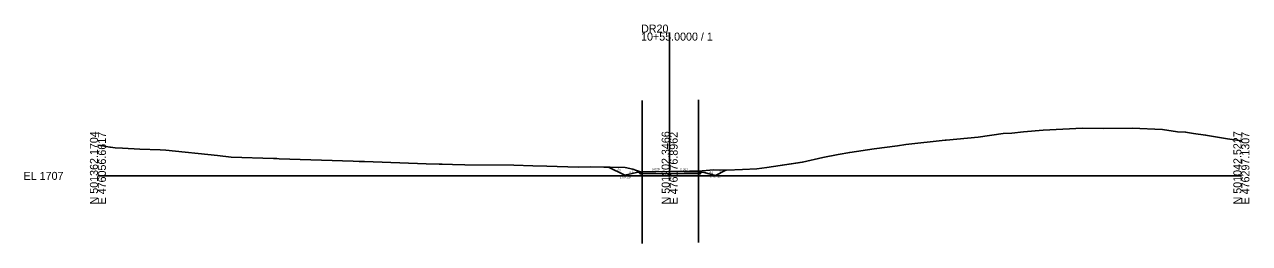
# Model space of a CAD drawing. Extents: x 78027 to 79855, y -93601 to -93005.
# Drawn here: x 78026.8 to 78455.3, y -93600.9 to -93524.2 of the extents above; entities that cross this region are included whole.
import ezdxf

# ---------------------------------------------------------------- set-up
doc = ezdxf.new("R2010")
doc.units = 0
for name, color, linetype in [('Exist Cross Section Cell', 7, 'Continuous'), ('Exist XS Center Line Elevation Label', 7, 'Continuous'), ('Exist XS Ground Line', 7, 'Continuous'), ('Prop XS Ditch Slope Text', 7, 'Continuous'), ('Prop XS Ditch Standard Text', 7, 'Continuous'), ('Prop XS Earthwork Shape', 7, 'Continuous'), ('Prop XS EOT Tick Mark', 7, 'Continuous'), ('Prop XS Finish Grade', 7, 'Continuous'), ('Prop XS Finish Grade Earthwork', 7, 'Continuous'), ('Prop XS Finish Grade Pavement', 7, 'Continuous'), ('Prop XS Pvmt Edge Slope', 7, 'Continuous'), ('Prop XS SE Text', 7, 'Continuous'), ('Prop XS Shoulder Borrow Shape', 7, 'Continuous'), ('Prop XS Side Slope Text', 7, 'Continuous'), ('Prop XS Subgrade Earthwork', 7, 'Continuous'), ('Scratch_Level_0', 7, 'Continuous'), ('Scratch_Level_4', 7, 'Continuous'), ('Scratch_Level_5', 7, 'Continuous'), ('Scratch_Level_6', 7, 'Continuous')]:
    doc.layers.add(name, color=color, linetype=linetype)

msp = doc.modelspace()

# ---------------------------------------------------------------- linework, layer by layer
at = {"layer": 'Exist Cross Section Cell'}
for p, q in [((78252.48, -93577.22), (78252.48, -93527.07)), ((78052.48, -93577.22), (78252.48, -93577.22)), ((78252.48, -93577.22), (78452.48, -93577.22))]:
    msp.add_line(p, q, dxfattribs=at)
at = {"layer": 'Exist XS Ground Line'}
for p, q in [((78376.27, -93561.79), (78383.1, -93561.24)), ((78383.1, -93561.24), (78396.9, -93560.55)), ((78396.9, -93560.55), (78404.42, -93560.58)), ((78404.42, -93560.58), (78414.28, -93560.5)), ((78414.28, -93560.5), (78424.94, -93561.02)), ((78424.94, -93561.02), (78430.15, -93561.75)), ((78335.05, -93566.25), (78348.83, -93564.73)), ((78348.83, -93564.73), (78349.16, -93564.7)), ((78349.16, -93564.7), (78360.37, -93563.66)), ((78360.37, -93563.66), (78369.1, -93562.44)), ((78369.1, -93562.44), (78372.19, -93562.24)), ((78372.19, -93562.24), (78376.27, -93561.79)), ((78430.15, -93561.75), (78432.97, -93561.87)), ((78432.97, -93561.87), (78435.77, -93562.4)), ((78435.77, -93562.4), (78439.95, -93562.93)), ((78439.95, -93562.93), (78447.6, -93564.25)), ((78447.6, -93564.25), (78452.48, -93565.01)), ((78052.48, -93566.51), (78053.5, -93566.59)), ((78053.5, -93566.59), (78054.08, -93566.65)), ((78054.08, -93566.65), (78056.61, -93567.15)), ((78056.61, -93567.15), (78056.93, -93567.19)), ((78056.93, -93567.19), (78058.54, -93567.38)), ((78058.54, -93567.38), (78061.04, -93567.5)), ((78061.04, -93567.5), (78067.08, -93567.88)), ((78067.08, -93567.88), (78074.23, -93568.09)), ((78074.23, -93568.09), (78076.18, -93568.19)), ((78076.18, -93568.19), (78094.33, -93570.14)), ((78306.07, -93570.81), (78311.48, -93569.76)), ((78311.48, -93569.76), (78315.51, -93568.98)), ((78315.51, -93568.98), (78324, -93567.81)), ((78324, -93567.81), (78332.15, -93566.72)), ((78332.15, -93566.72), (78335.05, -93566.25)), ((78094.33, -93570.14), (78099.14, -93570.63)), ((78099.14, -93570.63), (78113.88, -93571.15)), ((78113.88, -93571.15), (78114.68, -93571.19)), ((78114.68, -93571.19), (78115.12, -93571.19)), ((78115.12, -93571.19), (78115.87, -93571.21)), ((78115.87, -93571.21), (78141.82, -93572.08)), ((78141.82, -93572.08), (78143.84, -93572.14)), ((78143.84, -93572.14), (78145.77, -93572.18)), ((78145.77, -93572.18), (78167.26, -93572.98)), ((78167.26, -93572.98), (78171.85, -93573.11)), ((78171.85, -93573.11), (78172.92, -93573.12)), ((78172.92, -93573.12), (78176.48, -93573.28)), ((78176.48, -93573.28), (78180.8, -93573.32)), ((78180.8, -93573.32), (78198.01, -93573.52)), ((78198.01, -93573.52), (78204.61, -93573.74)), ((78204.61, -93573.74), (78209.53, -93573.8)), ((78209.53, -93573.8), (78220.48, -93574.16)), ((78220.48, -93574.16), (78224.92, -93574.06)), ((78224.92, -93574.06), (78229.49, -93574.2)), ((78229.49, -93574.2), (78231.67, -93574.12)), ((78231.67, -93574.12), (78236.86, -93574.29)), ((78236.86, -93574.29), (78239.63, -93574.89)), ((78282.92, -93574.78), (78286.45, -93574.34)), ((78286.45, -93574.34), (78298.88, -93572.44)), ((78298.88, -93572.44), (78298.97, -93572.41)), ((78298.97, -93572.41), (78306.07, -93570.81)), ((78239.63, -93574.89), (78240.83, -93575.37)), ((78240.83, -93575.37), (78241.94, -93575.67)), ((78241.94, -93575.67), (78242.84, -93575.89)), ((78242.84, -93575.89), (78252.41, -93575.67)), ((78252.41, -93575.67), (78252.48, -93575.67)), ((78252.48, -93575.67), (78259.43, -93575.62)), ((78259.43, -93575.62), (78262.52, -93575.55)), ((78262.52, -93575.55), (78267.84, -93575.08)), ((78267.84, -93575.08), (78272.44, -93575.21)), ((78272.44, -93575.21), (78277.97, -93574.99)), ((78277.97, -93574.99), (78282.92, -93574.78))]:
    msp.add_line(p, q, dxfattribs=at)
at = {"layer": 'Prop XS Earthwork Shape'}
msp.add_lwpolyline([(78231.09, -93574.15), (78231.67, -93574.12), (78236.86, -93574.29), (78239.63, -93574.89), (78240.83, -93575.37), (78241.94, -93575.67), (78242.84, -93575.89), (78252.41, -93575.67), (78252.48, -93575.67), (78259.43, -93575.62), (78262.52, -93575.55), (78267.84, -93575.08), (78272.19, -93575.2), (78268.53, -93577.03), (78264.53, -93576.03), (78263.79, -93575.97), (78263.21, -93576.55), (78262.52, -93576.53), (78252.48, -93576.33), (78242.84, -93576.53), (78242.16, -93576.54), (78241.58, -93575.96), (78240.84, -93576.02), (78236.84, -93577.02)], close=True, dxfattribs=at)
msp.add_lwpolyline([(78231.09, -93574.15), (78231.67, -93574.12), (78236.86, -93574.29), (78239.63, -93574.89), (78240.83, -93575.37), (78241.94, -93575.67), (78242.84, -93575.89), (78252.41, -93575.67), (78252.48, -93575.67), (78259.43, -93575.62), (78262.52, -93575.55), (78267.84, -93575.08), (78272.19, -93575.2), (78268.53, -93577.03), (78264.53, -93576.03), (78263.79, -93575.97), (78263.21, -93576.55), (78262.52, -93576.53), (78252.48, -93576.33), (78242.84, -93576.53), (78242.16, -93576.54), (78241.58, -93575.96), (78240.84, -93576.02), (78236.84, -93577.02)], close=True, dxfattribs=at)
at = {"layer": 'Prop XS EOT Tick Mark'}
for p, q in [((78242.84, -93575.86), (78242.84, -93574.86)), ((78262.52, -93575.87), (78262.52, -93574.87))]:
    msp.add_line(p, q, dxfattribs=at)
at = {"layer": 'Prop XS Finish Grade'}
for p, q in [((78242.84, -93575.86), (78241.58, -93575.96)), ((78262.52, -93575.87), (78263.79, -93575.97))]:
    msp.add_line(p, q, dxfattribs=at)
at = {"layer": 'Prop XS Finish Grade Earthwork'}
for p, q in [((78236.84, -93577.02), (78231.09, -93574.15)), ((78240.84, -93576.02), (78236.84, -93577.02)), ((78241.58, -93575.96), (78240.84, -93576.02)), ((78263.79, -93575.97), (78264.53, -93576.03)), ((78264.53, -93576.03), (78268.53, -93577.03)), ((78268.53, -93577.03), (78272.19, -93575.2))]:
    msp.add_line(p, q, dxfattribs=at)
at = {"layer": 'Prop XS Finish Grade Pavement'}
for p, q in [((78242.84, -93575.86), (78252.48, -93575.67)), ((78252.48, -93575.67), (78262.52, -93575.87))]:
    msp.add_line(p, q, dxfattribs=at)
at = {"layer": 'Prop XS Pvmt Edge Slope'}
for p, q in [((78242.84, -93575.86), (78242.16, -93576.54)), ((78262.52, -93575.87), (78263.21, -93576.55))]:
    msp.add_line(p, q, dxfattribs=at)
at = {"layer": 'Prop XS Shoulder Borrow Shape'}
for points in [[(78242.74, -93575.87), (78242.81, -93575.88), (78242.16, -93576.54), (78241.58, -93575.96)], [(78242.74, -93575.87), (78242.81, -93575.88), (78242.84, -93575.86)], [(78263.21, -93576.55), (78263.79, -93575.97), (78262.52, -93575.87)]]:
    msp.add_lwpolyline(points, close=True, dxfattribs=at)
at = {"layer": 'Prop XS Subgrade Earthwork'}
for p, q in [((78242.16, -93576.54), (78241.58, -93575.96)), ((78242.84, -93576.53), (78242.16, -93576.54)), ((78252.48, -93576.33), (78242.84, -93576.53)), ((78262.52, -93576.53), (78252.48, -93576.33)), ((78262.52, -93576.53), (78263.21, -93576.55)), ((78263.21, -93576.55), (78263.79, -93575.97))]:
    msp.add_line(p, q, dxfattribs=at)
at = {"layer": 'Scratch_Level_0'}
msp.add_lwpolyline([(78052.48, -93566.51), (78053.5, -93566.59), (78054.08, -93566.65), (78056.61, -93567.15), (78056.93, -93567.19), (78058.54, -93567.38), (78061.04, -93567.5), (78067.08, -93567.88), (78074.23, -93568.09), (78076.18, -93568.19), (78094.33, -93570.14), (78099.14, -93570.63), (78113.88, -93571.15), (78114.68, -93571.19), (78115.12, -93571.19), (78115.87, -93571.21), (78141.82, -93572.08), (78143.84, -93572.14), (78145.77, -93572.18), (78167.26, -93572.98), (78171.85, -93573.11), (78172.92, -93573.12), (78176.48, -93573.28), (78180.8, -93573.32), (78198.01, -93573.52), (78204.61, -93573.74), (78209.53, -93573.8), (78220.48, -93574.16), (78224.92, -93574.06), (78229.49, -93574.2), (78231.67, -93574.12), (78236.86, -93574.29), (78239.63, -93574.89), (78240.83, -93575.37), (78241.94, -93575.67), (78242.84, -93575.89), (78252.48, -93575.67), (78259.43, -93575.62), (78262.52, -93575.55), (78267.84, -93575.08), (78272.44, -93575.21), (78277.97, -93574.99), (78282.92, -93574.78), (78286.45, -93574.34), (78298.97, -93572.41), (78306.07, -93570.81), (78311.48, -93569.76), (78315.51, -93568.98), (78324, -93567.81), (78332.15, -93566.72), (78335.05, -93566.25), (78348.83, -93564.73), (78349.16, -93564.7), (78360.37, -93563.66), (78369.1, -93562.44), (78372.19, -93562.24), (78376.27, -93561.79), (78383.1, -93561.24), (78396.9, -93560.55), (78404.42, -93560.58), (78414.28, -93560.5), (78424.94, -93561.02), (78430.15, -93561.75), (78432.97, -93561.87), (78435.77, -93562.4), (78439.95, -93562.93), (78447.6, -93564.25), (78452.48, -93565.01)], dxfattribs=at)
at = {"layer": 'Scratch_Level_4'}
for p, q in [((78242.84, -93550.89), (78242.84, -93600.89)), ((78242.84, -93550.89), (78242.84, -93600.89)), ((78262.52, -93550.55), (78262.52, -93600.55)), ((78262.52, -93550.55), (78262.52, -93600.55))]:
    msp.add_line(p, q, dxfattribs=at)
at = {"layer": 'Scratch_Level_5'}
msp.add_lwpolyline([(78052.48, -93566.51), (78053.5, -93566.59), (78054.08, -93566.65), (78056.61, -93567.15), (78056.93, -93567.19), (78058.54, -93567.38), (78061.04, -93567.5), (78067.08, -93567.88), (78074.23, -93568.09), (78076.18, -93568.19), (78094.33, -93570.14), (78099.14, -93570.63), (78113.88, -93571.15), (78114.68, -93571.19), (78115.12, -93571.19), (78115.87, -93571.21), (78141.82, -93572.08), (78143.84, -93572.14), (78145.77, -93572.18), (78167.26, -93572.98), (78171.85, -93573.11), (78172.92, -93573.12), (78176.48, -93573.28), (78180.8, -93573.32), (78198.01, -93573.52), (78204.61, -93573.74), (78209.53, -93573.8), (78220.48, -93574.16), (78224.92, -93574.06), (78229.49, -93574.2), (78231.67, -93574.12), (78236.86, -93574.29), (78239.63, -93574.89), (78240.83, -93575.37), (78241.94, -93575.67), (78242.84, -93575.89), (78252.48, -93575.67), (78259.43, -93575.62), (78262.52, -93575.55), (78267.84, -93575.08), (78272.44, -93575.21), (78277.97, -93574.99), (78282.92, -93574.78), (78286.45, -93574.34), (78298.97, -93572.41), (78306.07, -93570.81), (78311.48, -93569.76), (78315.51, -93568.98), (78324, -93567.81), (78332.15, -93566.72), (78335.05, -93566.25), (78348.83, -93564.73), (78349.16, -93564.7), (78360.37, -93563.66), (78369.1, -93562.44), (78372.19, -93562.24), (78376.27, -93561.79), (78383.1, -93561.24), (78396.9, -93560.55), (78404.42, -93560.58), (78414.28, -93560.5), (78424.94, -93561.02), (78430.15, -93561.75), (78432.97, -93561.87), (78435.77, -93562.4), (78439.95, -93562.93), (78447.6, -93564.25), (78452.48, -93565.01)], dxfattribs=at)
at = {"layer": 'Scratch_Level_6'}
msp.add_lwpolyline([(78052.48, -93566.51), (78053.5, -93566.59), (78054.08, -93566.65), (78056.61, -93567.15), (78056.93, -93567.19), (78058.54, -93567.38), (78061.04, -93567.5), (78067.08, -93567.88), (78074.23, -93568.09), (78076.18, -93568.19), (78094.33, -93570.14), (78099.14, -93570.63), (78113.88, -93571.15), (78114.68, -93571.19), (78115.12, -93571.19), (78115.87, -93571.21), (78141.82, -93572.08), (78143.84, -93572.14), (78145.77, -93572.18), (78167.26, -93572.98), (78171.85, -93573.11), (78172.92, -93573.12), (78176.48, -93573.28), (78180.8, -93573.32), (78198.01, -93573.52), (78204.61, -93573.74), (78209.53, -93573.8), (78220.48, -93574.16), (78224.92, -93574.06), (78229.49, -93574.2), (78231.67, -93574.12), (78236.86, -93574.29), (78239.63, -93574.89), (78240.83, -93575.37), (78241.94, -93575.67), (78242.84, -93575.89), (78252.48, -93575.67), (78259.43, -93575.62), (78262.52, -93575.55), (78267.84, -93575.08), (78272.44, -93575.21), (78277.97, -93574.99), (78282.92, -93574.78), (78286.45, -93574.34), (78298.97, -93572.41), (78306.07, -93570.81), (78311.48, -93569.76), (78315.51, -93568.98), (78324, -93567.81), (78332.15, -93566.72), (78335.05, -93566.25), (78348.83, -93564.73), (78349.16, -93564.7), (78360.37, -93563.66), (78369.1, -93562.44), (78372.19, -93562.24), (78376.27, -93561.79), (78383.1, -93561.24), (78396.9, -93560.55), (78404.42, -93560.58), (78414.28, -93560.5), (78424.94, -93561.02), (78430.15, -93561.75), (78432.97, -93561.87), (78435.77, -93562.4), (78439.95, -93562.93), (78447.6, -93564.25), (78452.48, -93565.01)], dxfattribs=at)

# ---------------------------------------------------------------- texts
at = {"layer": 'Exist Cross Section Cell'}
for s, p in [('10+55.0000 / 1', (78242.48, -93529.87)), ('DR20', (78242.48, -93527.07)), ('EL 1707', (78026.48, -93578.62))]:
    msp.add_text(s, height=2.8, dxfattribs=at).set_placement(p)
for s, p in [('N 501362.1704', (78052.48, -93587.22)), ('E 476056.6617', (78055.28, -93587.22)), ('N 501202.3466', (78252.48, -93587.22)), ('E 476176.8962', (78255.28, -93587.22)), ('N 501042.5227', (78452.48, -93587.22)), ('E 476297.1307', (78455.28, -93587.22))]:
    msp.add_text(s, height=2.8, rotation=90, dxfattribs=at).set_placement(p)
at = {"layer": 'Exist XS Center Line Elevation Label'}
msp.add_text('1708.55', height=0.75, dxfattribs=at).set_placement((78250.7, -93577.52))
at = {"layer": 'Prop XS Ditch Slope Text'}
for rotation, p in [(14.0347, (78238.47, -93576.3)), (345.9752, (78266.31, -93576.2))]:
    msp.add_text('4:1', height=0.75, rotation=rotation, dxfattribs=at).set_placement(p)
at = {"layer": 'Prop XS Ditch Standard Text'}
for s, p in [('1707.20', (78235.02, -93578.04)), ('1707.19', (78266.59, -93577.72))]:
    msp.add_text(s, height=0.75, dxfattribs=at).set_placement(p)
at = {"layer": 'Prop XS SE Text'}
for rotation, p in [(1.1458, (78246.35, -93575.29)), (358.8542, (78256.19, -93575.24))]:
    msp.add_text('0.020', height=0.75, rotation=rotation, dxfattribs=at).set_placement(p)
at = {"layer": 'Prop XS Side Slope Text'}
for rotation, p in [(333.4376, (78234.1, -93575.21)), (26.5455, (78270.08, -93576.12))]:
    msp.add_text('2:1', height=0.75, rotation=rotation, dxfattribs=at).set_placement(p)

doc.saveas('drawing.dxf')
